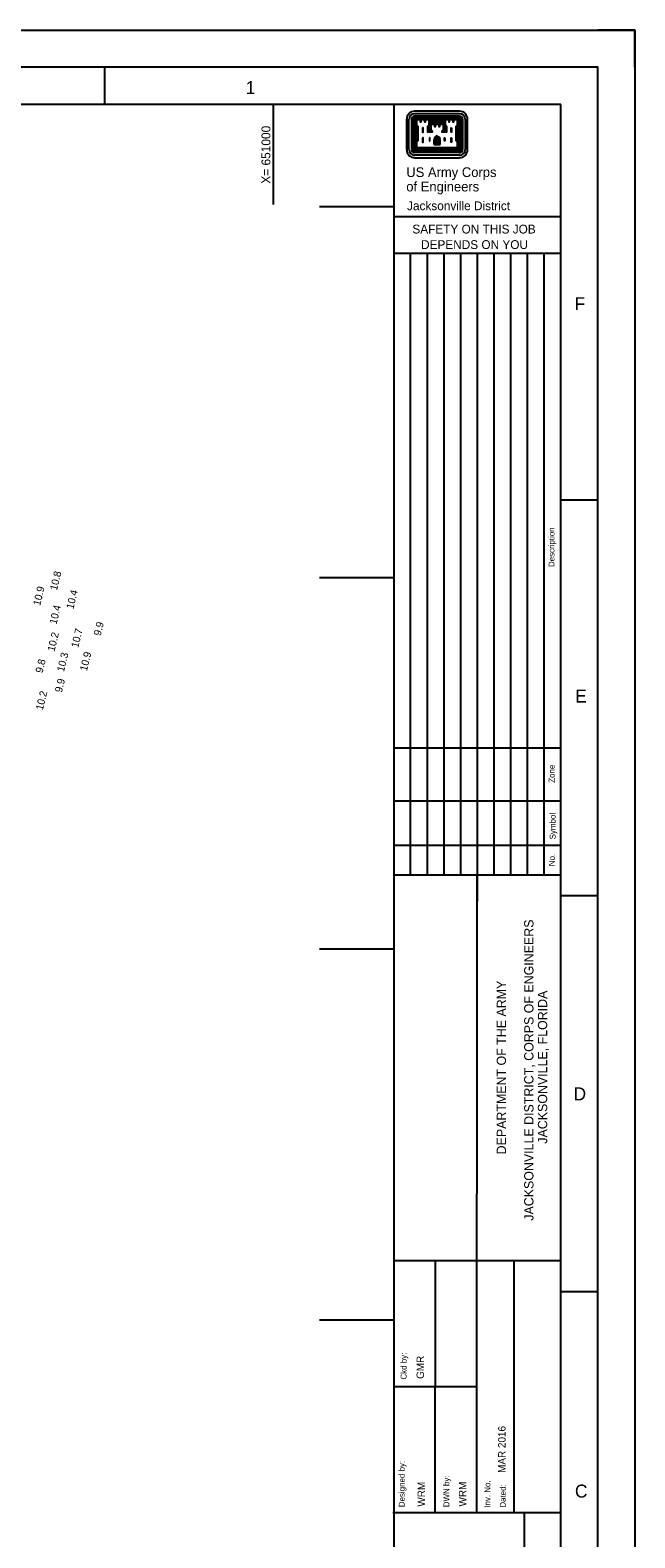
# Model space of a CAD drawing. Extents: x 647087 to 651487, y 788838 to 792238.
# Drawn here: x 650672 to 651487, y 790206 to 792238 of the extents above; entities that cross this region are included whole.
import ezdxf

# ---------------------------------------------------------------- set-up
doc = ezdxf.new("R2010")
doc.units = 0
for name, color, linetype in [('G-ANNO-NPLT', 7, 'Continuous'), ('G-ANNO-TEXT-DRWG', 7, 'Continuous'), ('G-ANNO-TEXT-LOGO', 7, 'Continuous'), ('G-ANNO-TEXT-PROJ', 7, 'Continuous'), ('G-ANNO-TEXT-TTLB', 7, 'Continuous'), ('G-ANNO-TTLB', 7, 'Continuous'), ('V-TOPO-COOR-STAT', 7, 'Continuous'), ('V-TOPO-SOUN', 7, 'Continuous')]:
    doc.layers.add(name, color=color, linetype=linetype)

msp = doc.modelspace()

# ---------------------------------------------------------------- linework, layer by layer
at = {"layer": 'G-ANNO-NPLT'}
msp.add_lwpolyline([(647087.3, 792237.8), (651487.3, 792237.8), (651487.3, 788837.9), (647087.3, 788837.9)], close=True, dxfattribs=at)
msp.add_lwpolyline([(651487.3, 792187.8), (651487.3, 792237.8), (651437.3, 792237.8)], dxfattribs=at)
at = {"layer": 'G-ANNO-TEXT-LOGO'}
for p, q in [((651179.6, 792117.8), (651179.6, 792076.8)), ((651182.8, 792076.8), (651182.8, 792117.8)), ((651186.3, 792117.8), (651186.3, 792076.8)), ((651187.2, 792117.8), (651187.2, 792076.8)), ((651188, 792117.8), (651188, 792076.8)), ((651188.9, 792117.8), (651188.9, 792076.8)), ((651189.8, 792117.8), (651189.8, 792076.8)), ((651251.1, 792128.5), (651190.3, 792128.5)), ((651190.3, 792125.3), (651251.1, 792125.3)), ((651251.1, 792121.9), (651190.3, 792121.9)), ((651251.1, 792121), (651190.3, 792121)), ((651251.1, 792120.1), (651190.3, 792120.1)), ((651251.1, 792119.3), (651190.3, 792119.3)), ((651251.1, 792118.4), (651190.3, 792118.4)), ((651190.7, 792117.8), (651190.7, 792077.1)), ((651191.5, 792117.8), (651191.5, 792078)), ((651211.4, 792117.6), (651230, 792117.6)), ((651211.4, 792116.7), (651230, 792116.7)), ((651211.4, 792115.9), (651230, 792115.9)), ((651211.4, 792115), (651230, 792115)), ((651211.4, 792114.1), (651230, 792114.1)), ((651211.4, 792113.3), (651230, 792113.3)), ((651211.4, 792112.4), (651230, 792112.4)), ((651249.9, 792117.8), (651249.9, 792078)), ((651250.7, 792117.8), (651250.7, 792077.1)), ((651251.6, 792117.8), (651251.6, 792076.8)), ((651252.5, 792117.8), (651252.5, 792076.8)), ((651253.3, 792117.8), (651253.3, 792076.8)), ((651254.2, 792117.8), (651254.2, 792076.8)), ((651255.1, 792117.8), (651255.1, 792076.8)), ((651258.5, 792117.8), (651258.5, 792076.8)), ((651261.8, 792076.8), (651261.8, 792117.8)), ((651192.2, 792109.1), (651192.2, 792088.1)), ((651193.1, 792108.2), (651193.1, 792089.1)), ((651216.7, 792083.9), (651216.7, 792090.6)), ((651217.5, 792083.9), (651217.5, 792090.6)), ((651218.4, 792083.9), (651218.4, 792090.6)), ((651219.3, 792083.9), (651219.3, 792090.6)), ((651220.1, 792083.9), (651220.1, 792090.6)), ((651221.3, 792083.9), (651221.3, 792090.6)), ((651222.1, 792083.9), (651222.1, 792090.6)), ((651223, 792083.9), (651223, 792090.6)), ((651223.9, 792083.9), (651223.9, 792090.6)), ((651224.7, 792083.9), (651224.7, 792090.6)), ((651248.3, 792108.2), (651248.3, 792089.1)), ((651249.2, 792109), (651249.2, 792088.2)), ((651251.1, 792076.2), (651190.3, 792076.2)), ((651251.1, 792075.4), (651190.3, 792075.4)), ((651251.1, 792074.5), (651190.3, 792074.5)), ((651251.1, 792073.6), (651190.3, 792073.6)), ((651251.1, 792072.8), (651190.3, 792072.8)), ((651250.7, 792077.1), (651190.7, 792077.1)), ((651249.9, 792078), (651191.5, 792078)), ((651216.7, 792083.9), (651224.7, 792083.9)), ((651251.1, 792069.3), (651190.3, 792069.3)), ((651190.3, 792066), (651251.1, 792066))]:
    msp.add_line(p, q, dxfattribs=at)
for points in [[(651192.2, 792117.8), (651192.2, 792109.9), (651193.9, 792108.2), (651193.9, 792089.1), (651192.2, 792087.3), (651192.2, 792078.6), (651249.2, 792078.6), (651249.2, 792087.3), (651247.4, 792089.1), (651247.4, 792108.2), (651249.2, 792109.9), (651249.2, 792117.8), (651241.7, 792117.8), (651235.9, 792117.8), (651230.5, 792117.8), (651230.5, 792109.9), (651232.4, 792108.2), (651232.4, 792101.2), (651228.2, 792101.2), (651228.2, 792101.9), (651230, 792103.7), (651230, 792111.5), (651222.5, 792111.5), (651216.7, 792111.5), (651211.4, 792111.5), (651211.4, 792103.7), (651213.2, 792101.9), (651213.2, 792101.2), (651209, 792101.2), (651209, 792108.2), (651210.8, 792109.9), (651210.8, 792117.8), (651203.3, 792117.8), (651197.5, 792117.8), (651192.2, 792117.8)], [(651193, 792116.9), (651193, 792110.3), (651194.8, 792108.5), (651194.8, 792088.7), (651193, 792086.9), (651193, 792079.5), (651248.4, 792079.5), (651248.4, 792086.9), (651246.5, 792088.7), (651246.5, 792108.5), (651248.4, 792110.3), (651248.4, 792116.9), (651243, 792116.9), (651243, 792113.8), (651242.5, 792113.8), (651242.5, 792116.9), (651237.2, 792116.9), (651237.2, 792113.8), (651236.8, 792113.8), (651236.8, 792116.9), (651231.4, 792116.9), (651231.4, 792110.3), (651233.2, 792108.5), (651233.2, 792100.4), (651227.4, 792100.4), (651227.4, 792102.3), (651229.2, 792104.1), (651229.2, 792110.7), (651223.8, 792110.7), (651223.8, 792107.6), (651223.4, 792107.6), (651223.4, 792110.7), (651218, 792110.7), (651218, 792107.6), (651217.5, 792107.6), (651217.5, 792110.7), (651212.2, 792110.7), (651212.2, 792104.1), (651214, 792102.3), (651214, 792100.4), (651208.2, 792100.4), (651208.2, 792108.5), (651210, 792110.3), (651210, 792116.9), (651204.7, 792116.9), (651204.7, 792113.8), (651204.2, 792113.8), (651204.2, 792116.9), (651198.8, 792116.9), (651198.8, 792113.8), (651198.4, 792113.8), (651198.4, 792116.9), (651193, 792116.9)], [(651201.2, 792106.2), (651201.2, 792100.4), (651201.8, 792100.4), (651201.8, 792106.2), (651201.2, 792106.2)], [(651201.2, 792092.9), (651201.2, 792087), (651201.8, 792087), (651201.8, 792092.9), (651201.2, 792092.9)], [(651210.4, 792108.3), (651209.9, 792107.8), (651209.9, 792102.1), (651211.8, 792102.1), (651210.5, 792103.4), (651210.5, 792108.4)], [(651210.4, 792092.9), (651210.4, 792088.8), (651210.9, 792088.8), (651210.9, 792092.9), (651210.4, 792092.9)], [(651231, 792108.3), (651231.5, 792107.8), (651231.5, 792102.1), (651229.7, 792102.1), (651230.9, 792103.4), (651230.9, 792108.4)], [(651231, 792092.9), (651231, 792088.8), (651230.5, 792088.8), (651230.5, 792092.9), (651231, 792092.9)], [(651240.1, 792106.2), (651240.1, 792100.4), (651239.6, 792100.4), (651239.6, 792106.2), (651240.1, 792106.2)], [(651240.1, 792092.9), (651240.1, 792087), (651239.6, 792087), (651239.6, 792092.9), (651240.1, 792092.9)]]:
    msp.add_lwpolyline(points, dxfattribs=at)
for centre, major_axis, start_param, end_param in [((651190.4, 792117.8), (10.7, 0), 1.57078, 3.141576), ((651190.4, 792117.8), (7.49, 0), 1.57078, 3.141576), ((651190.4, 792117.8), (4.02, 0), 1.57078, 3.141576), ((651190.4, 792117.8), (3.15, 0), 1.57078, 3.141576), ((651190.4, 792117.8), (2.28, 0), 1.57078, 3.141576), ((651190.4, 792117.8), (1.41, 0), 1.57078, 3.141576), ((651190.4, 792117.8), (0.546, 0), 1.57078, 3.141576), ((651251.1, 792117.8), (10.7, 0), 6.283169, 7.853965), ((651251.1, 792117.8), (7.49, 0), 6.28317, 7.853966), ((651251.1, 792117.8), (4.02, 0), 6.283169, 7.853965), ((651251.1, 792117.8), (3.15, 0), 6.283169, 7.853965), ((651251.1, 792117.8), (2.28, 0), 6.283169, 7.853965), ((651251.1, 792117.8), (1.41, 0), 6.283169, 7.853965), ((651251.1, 792117.8), (0.546, 0), 6.283169, 7.853965), ((651222.2, 792090.1), (-5.55, 0), 4.985832, 6.214359), ((651222.2, 792090.1), (-4.69, 0), 4.947465, 6.21436), ((651222.2, 792090.1), (-3.82, 0), 4.947465, 6.21436), ((651222.2, 792090.1), (-2.95, 0), 4.947465, 6.21436), ((651219.2, 792090.1), (2.08, 0), 0.068794, 1.335689), ((651219.2, 792090.1), (2.95, 0), 0.068794, 1.335689), ((651219.2, 792090.1), (3.82, 0), 0.068795, 1.335689), ((651222.2, 792090.1), (-2.08, 0), 4.947465, 6.214359), ((651219.2, 792090.1), (4.69, 0), 0.068795, 1.335689), ((651219.2, 792090.1), (5.55, 0), 0.068795, 1.29842), ((651190.4, 792076.7), (-10.7, 0), 6.28317, 7.853966), ((651190.4, 792076.7), (-7.49, 0), 6.28317, 7.853966), ((651190.4, 792076.7), (-4.02, 0), 6.28317, 7.853966), ((651190.4, 792076.7), (-3.15, 0), 6.28317, 7.853966), ((651190.4, 792076.7), (-2.28, 0), 6.28317, 7.853966), ((651190.4, 792076.7), (-1.41, 0), 6.28317, 7.853966), ((651190.4, 792076.7), (-0.546, 0), 6.28317, 7.853966), ((651251.1, 792076.7), (4.02, 0), 4.712373, 6.28317), ((651251.1, 792076.7), (3.15, 0), 4.712373, 6.28317), ((651251.1, 792076.7), (2.28, 0), 4.712373, 6.28317), ((651251.1, 792076.7), (1.41, 0), 4.712373, 6.28317), ((651251.1, 792076.7), (0.546, 0), 4.712373, 6.28317), ((651251.1, 792076.7), (10.7, 0), 4.712373, 6.28317), ((651251.1, 792076.7), (-7.49, 0), 1.570781, 3.141577)]:
    msp.add_ellipse(centre, major_axis=major_axis, ratio=0.99964, start_param=start_param, end_param=end_param, dxfattribs=at)
at = {"layer": 'G-ANNO-TTLB'}
for p, q in [((650772.3, 792187.8), (650772.3, 792137.8)), ((651162.2, 792137.8), (651162.2, 788937.9)), ((651162.3, 791986.6), (651387.3, 791986.6)), ((651161.7, 791937.5), (651386.7, 791937.5)), ((651184.6, 791937.5), (651184.6, 791099.6)), ((651207.1, 791937.5), (651207.1, 791099.6)), ((651229.6, 791937.5), (651229.6, 791099.6)), ((651252.1, 791937.5), (651252.1, 791099.6)), ((651274.6, 791937.5), (651274.6, 791099.6)), ((651297.1, 791937.5), (651297.1, 791099.6)), ((651319.6, 791937.5), (651319.6, 791099.6)), ((651342.1, 791937.5), (651342.1, 791099.6)), ((651364.6, 791937.5), (651364.6, 791099.6)), ((651437.3, 791604.3), (651387.3, 791604.3)), ((651162.3, 791270.6), (651387.3, 791270.6)), ((651162.3, 791199.4), (651387.3, 791199.4)), ((651162.3, 791139.4), (651387.3, 791139.4)), ((651162.3, 791099.6), (651387.3, 791099.6)), ((651274.1, 790240), (651274.8, 791099.6)), ((651274.8, 791099.6), (651274.7, 791064.2)), ((651437.3, 791071), (651387.3, 791071)), ((651161.5, 790579.7), (651387.3, 790579.7)), ((651218.2, 790240.1), (651218.4, 790579.7)), ((651324.3, 790579.7), (651324.3, 790240)), ((651437.3, 790537.7), (651387.3, 790537.7)), ((651161.5, 790409.8), (651274.2, 790409.8)), ((651161.1, 790240), (651387.3, 790240)), ((651338, 790240), (651338, 789888.6))]:
    msp.add_line(p, q, dxfattribs=at)
for points in [[(647137.3, 788887.9), (651437.3, 788887.9), (651437.3, 792187.8), (647137.3, 792187.8)], [(651387.3, 792137.8), (647262.3, 792137.8), (647262.3, 788937.9), (651387.3, 788937.9)]]:
    msp.add_lwpolyline(points, close=True, dxfattribs=at)
at = {"layer": 'V-TOPO-COOR-STAT'}
for p, q in [((651000, 792002.8), (651000, 792137.8)), ((651062.2, 792000), (651162.2, 792000)), ((651062.2, 791500), (651162.2, 791500)), ((651062.2, 791000), (651162.2, 791000)), ((651062.2, 790500), (651162.2, 790500))]:
    msp.add_line(p, q, dxfattribs=at)

# ---------------------------------------------------------------- texts
at = {"layer": 'G-ANNO-TEXT-DRWG'}
for s, p in [('GMR', (651203, 790420.2)), ('WRM', (651204.5, 790248.1)), ('WRM', (651260.1, 790248.3))]:
    msp.add_text(s, height=10, rotation=90, dxfattribs=at).set_placement(p)
at = {"layer": 'G-ANNO-TEXT-PROJ'}
msp.add_text('MAR 2016', height=10, rotation=90, dxfattribs=at).set_placement((651313, 790293.6))
at = {"layer": 'G-ANNO-TEXT-TTLB'}
for s, height, p in [('US Army Corps', 13.086, (651179.2, 792039.9)), ('of Engineers', 13.086, (651179.2, 792020.5)), ('Jacksonville District', 11.9, (651180.2, 791995.2)), ('SAFETY ON THIS JOB', 11.9, (651187.4, 791963.8)), ('DEPENDS ON YOU', 11.9, (651199.1, 791942.9))]:
    msp.add_text(s, height=height, dxfattribs=at).set_placement(p)
for s, height, p in [('Description', 8, (651378.9, 791514.3)), ('Zone', 8, (651379.2, 791223.6)), ('Symbol', 8, (651380.4, 791147.3)), ('No.', 8, (651379.4, 791111.2)), ('JACKSONVILLE DISTRICT, CORPS OF ENGINEERS', 12.5, (651350.6, 790633.4)), ('DEPARTMENT OF THE ARMY', 12.5, (651313.6, 790722.8)), ('JACKSONVILLE, FLORIDA', 12.5, (651369.1, 790737.2)), ('Ckd by:', 8, (651179.5, 790419.3)), ('Designed by:', 8, (651177.1, 790247.3)), ('DWN by:', 8, (651237.3, 790247.3)), ('Inv. No.', 8, (651292.5, 790246.6)), ('Dated:', 8, (651313.3, 790246.7))]:
    msp.add_text(s, height=height, rotation=90, dxfattribs=at).set_placement(p)
at = {"layer": 'G-ANNO-TTLB'}
for s, p in [('1', (650962.7, 792151.7)), ('F', (651406, 791860.5)), ('E', (651406.8, 791331.7)), ('D', (651404.6, 790795.6)), ('C', (651406.5, 790260.3))]:
    msp.add_text(s, height=17.5, dxfattribs=at).set_placement(p)
at = {"layer": 'V-TOPO-COOR-STAT'}
msp.add_text('X= 651000', height=12, rotation=90, dxfattribs=at).set_placement((650996, 792030.9))
at = {"layer": 'V-TOPO-SOUN'}
for s, p in [('10.8 ', (650708.3, 791482.1)), ('10.9 ', (650685.6, 791461.6)), ('10.4 ', (650730.4, 791456.9)), ('10.4 ', (650707.6, 791436.4)), ('9.9', (650767.2, 791421)), ('10.2 ', (650704.9, 791399.8)), ('10.7 ', (650736.9, 791404.9)), ('10.9 ', (650748.6, 791373.4)), ('9.8', (650688.8, 791370.8)), ('10.3 ', (650717.7, 791372.5)), ('9.9', (650714.9, 791344.5)), ('10.2 ', (650689.2, 791320.7))]:
    msp.add_text(s, height=10, rotation=76.16, dxfattribs=at).set_placement(p)

doc.saveas('drawing.dxf')
